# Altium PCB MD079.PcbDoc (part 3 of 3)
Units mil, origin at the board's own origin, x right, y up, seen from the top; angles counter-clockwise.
Board outline 4255 x 2850 mil, 4 copper layers (Top Layer, Ground, Power, Bottom Layer), stack 61.6 mil thick; 171 components, 88 nets, 422 pads, 405 vias.
Unrouted connection lines stored in the file: 3.
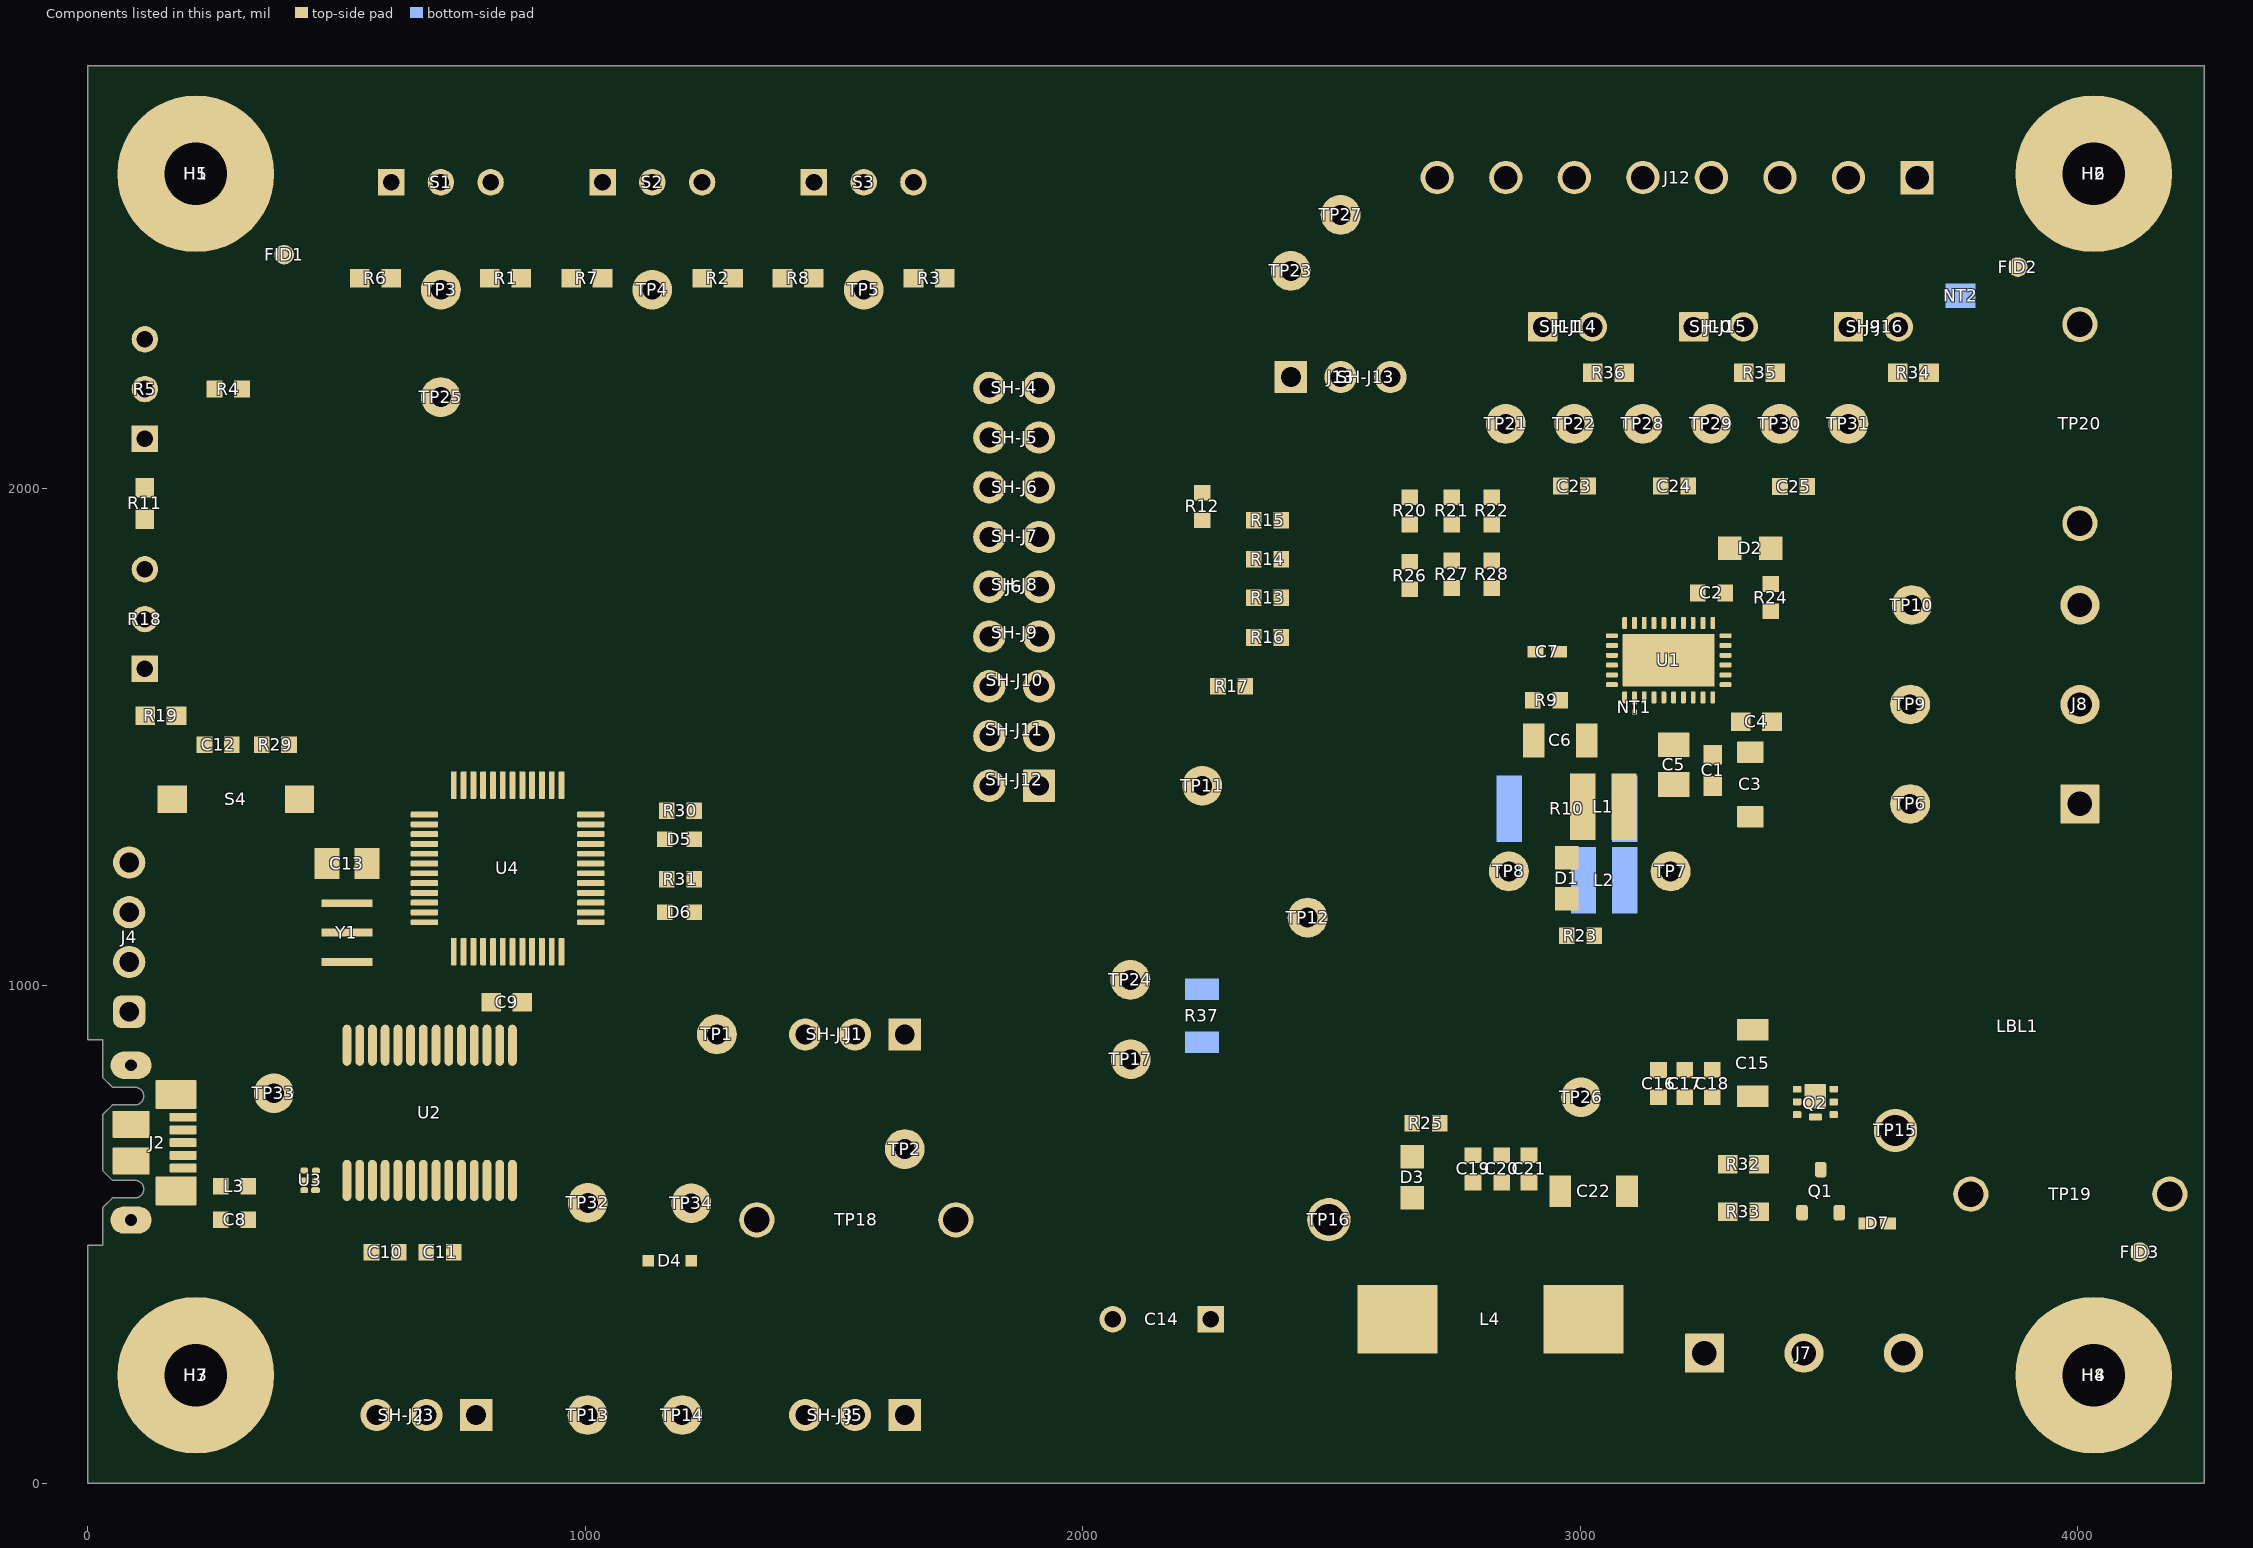
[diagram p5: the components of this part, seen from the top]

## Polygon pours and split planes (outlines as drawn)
VBK on Top Layer "TOP_LAYER_VBK_P051" (solid, remove dead copper, pour order 51): 2777.5,1175 3044.77,1175 3044.77,1452.44 3141.5,1560 3007.68,1560 2960.57,1512.89 2960.57,1435.66 2777.5,1275
NetD7_2 on Top Layer "TOP_LAYER_NETD7_2_P048" (solid, pour order 48): 3497.9,578.68 3497.9,500 3598.21,500 3598.21,578.68
NetQ1_1 on Top Layer "TOP_LAYER_NETQ1_1_P045" (solid, pour order 45): 3322.91,578.68 3322.91,500 3492.61,500 3492.61,578.68
5V_USB on Top Layer "TOP_LAYER_5V_USB_P043" (solid, pour order 43): 305,617.5 305,490 390,490 390,617.5
NetJ2_1 on Top Layer "TOP_LAYER_NETJ2_1_P044" (solid, remove dead copper, pour order 44): 170,650 340,650 340,565 170,565
NetC15_1 on Top Layer "TOP_LAYER_NETC15_1_P046" (solid, pour order 46): 3520,802.5 3130,802.5 3130,650 3422.5,650 3422.5,750 3520,750
NetQ1_3 on Top Layer "TOP_LAYER_NETQ1_3_P047" (solid, remove dead copper, pour order 47): 3322.91,685 3322.91,584.04 3517.5,584.04 3517.5,685 3450,685 3450,750 3422.5,750 3422.5,685
NetC15_1 on Top Layer "TOP_LAYER_NETC15_1_P049" (solid, pour order 49): 2830,490 3100,490 3100,232.5 2830,232.5
VM on Top Layer "TOP_LAYER_VM_P050" (solid, pour order 50): 2170,625 3000,625 3000,277.5 3187.5,277.5 3187.5,330 3317.5,330 3317.5,122.5 2170,122.5
PGND on Top Layer "TOP_LAYER_PGND_P070" (solid, remove dead copper, pour order 70): 4255,0 1865,0 1865,939.48 1864.48,940 3245.87,940 3245.87,1691.58 3767.5,2213.21 3767.5,2850 4255,2850
AGND on Top Layer "TOP_LAYER_AGND_P075" (solid, remove dead copper, pour order 75): 0,0 1865,0 1865,939.78 1865.22,940 3245.87,940 3245.87,1691.58 3767.5,2213.21 3767.5,2850 0,2850
AVDD on Top Layer "TOP_LAYER_AVDD_P066" (solid, pour order 66): 80,2132.5 150,2132.5 150,1965 80,1965
AVDD on Top Layer "TOP_LAYER_AVDD_P065" (solid, remove dead copper, pour order 65): 3217.71,1713.44 3239.75,1713.44 3239.75,1765.58 3240,1765.83 3269.86,1765.83 3269.86,1813.33 3327.5,1813.33 3327.5,1914.73 3217.71,1914.73
AVDD on Top Layer "TOP_LAYER_AVDD_P061" (solid, pour order 61): 2850.73,2030 2850.73,1965 2217.5,1965 2217.5,2030
OUTC on Top Layer "TOP_LAYER_OUTC_P057" (solid, pour order 57): 3275,1654.84 3401.91,1661.73 3600,1865 4120,1865 4120,1665 3600,1665 3420,1640 3275,1640
OUTA on Top Layer "TOP_LAYER_OUTA_P058" (solid, pour order 58): 3275,1612.5 3275,1595 3400,1585 3600,1265 4120,1265 4120,1465 3600,1465 3420,1612.5
OUTB on Top Layer "TOP_LAYER_OUTB_P056" (solid, pour order 56): 3275,1635 3420,1635 3600,1665 4120,1665 4120,1465 3600,1465 3420,1615 3275,1615
SW_BUCK on Top Layer "TOP_LAYER_SW_BUCK_P052" (solid, remove dead copper, pour order 52): 3050,1175 3240,1175 3240,1375 3150,1375 3150,1560 3050,1450
VM on Top Layer "TOP_LAYER_VM_P053" (solid, remove dead copper, pour order 53): 3220,1595 3220,1370 3400,1370 3400,1505 3351.12,1505 3351.12,1563.35 3260,1563.35 3260,1595
VBAT on Top Layer "TOP_LAYER_VBAT_P054" (solid, remove dead copper, pour order 54): 3605,580 3450,580 3450,802.5 3732.5,802.5 3732.5,172.5 3605,172.5
5VCC on Top Layer "TOP_LAYER_5VCC_P055" (solid, pour order 55): 605,490 705,490 705,442.5 605,442.5
AGND on Bottom Layer "BOTTOM_LAYER_AGND_P076" (solid, remove dead copper, pour order 76): 0,2850 3767.5,2850 3767.5,2203.16 3276.25,1711.91 3276.33,1047.64 3168.69,940 1865,940 1865,0 0,0
PGND on Bottom Layer "Bottom Layer-PGND" (solid, remove dead copper, pour order 74): 1865,940 1865,0 4255,0 4255,2850 3767.5,2850 3767.5,2203.16 3276.25,1711.91 3276.25,1049.4 3161.08,940
NetC15_1 on Bottom Layer "BOTTOM_LAYER_NETC15_1_P073" (solid, pour order 73): 2830,232.5 3155,232.5 3155,592.5 3422.5,592.5 3422.5,822.5 3130,822.5 3130,706.97 2830,706.97
5V_USB on Bottom Layer "BOTTOM_LAYER_5V_USB_P071" (solid, pour order 71): 440,495 315,495 315,840.51 440,840.51
VBK on Bottom Layer "BOTTOM_LAYER_VBK_P060" (solid, pour order 60): 3044.59,1450 2791.61,1450 2791.61,1137.5 3044.77,1137.5
SW_BUCK on Bottom Layer "BOTTOM_LAYER_SW_BUCK_P059" (solid, pour order 59): 3050,1450 3131.87,1450 3252.5,1330 3252.5,1137.5 3050,1137.5
AGND on Power "POWER_AGND_P069" (solid, remove dead copper, pour order 69): 0,2850 0,0 4255,0 4255,2850
VBK on Power "POWER_VBK_P068" (solid, remove dead copper, pour order 68): 2575,2297.5 2575,1540 2791.61,1275 2791.61,1152.5 2918.19,1152.5 2918.19,1275 2691.24,1540 2691.24,2297.5
AVDD on Power "POWER_AVDD_P067" (solid, pour order 67): 2837.5,1557.5 2876.25,1557.5 2876.25,1792.5 3292.5,1792.5 3292.5,2057.5 3757.5,2057.5 3757.5,2290.5 2864.88,2290.5 2739.8,2387.5 1879.47,2387.5 1783.18,2490 672.5,2490 320,2137.5 80,2137.5 80,2065 370.4,2065 612.34,2302.5 1835,2302.5 2252.5,2302.5 2252.5,1963.92 2307.5,1963.92 2307.5,2302.5 2700,2302.5 2785,2235 2785,2057.5 3207.85,2057.5 3207.85,1864.38 2837.5,1864.38
VM on Power "POWER_VM_P064" (solid, pour order 64): 2707.5,630 2170,630 2170,122.5 3387.5,122.5 3387.5,1477.5 3045,1477.5 3045,1015
5V_USB on Power "POWER_5V_USB_P063" (solid, pour order 63): 315,617.5 440,617.5 440,495 315,495
3V3_MCU on Power "POWER_3V3_MCU_P062" (solid, pour order 62): 1495,85 1595,85 1595,206.16 1272.5,526.21 1272.5,815 1150.3,937.2 1150.3,1395 1050,1395 1050,1277.5 512.5,1277.5 512.5,1470 415,1470 415,1100 46.93,1100 46.93,1000 512.5,1000 512.5,1180 1050,1180 1050,885 1157.5,777.5 1157.5,495 1495,157.5
AGND on Ground "GROUND_AGND_P072" (solid, remove dead copper, pour order 72): 0,2850 4255,2850 4255,0 0,0

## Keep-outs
Keep-Out Layer:
  text ".Layer_Name" at -201.73,-1117.79 h60

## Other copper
Top Layer:
  region net VBK: 3125,1560 3095,1560 3095,1545 3125,1545
  text ".Layer_Name" at -201.73,-1117.79 h60
Bottom Layer:
  text ".Layer_Name" at -201.73,-1117.79 h60

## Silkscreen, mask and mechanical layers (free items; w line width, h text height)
Top Overlay:
  lines w8: 505.04,61.69 846.71,61.38 846.96,406.6 505.28,406.91 505.04,63.84 ; 1367.28,62.4 1707.33,62.1 1707.57,412.11 1367.53,412.41 1367.28,64.56 ; 1862.5,2850 1865,7.5 ; 1907.28,2490.58 1908.82,2735.02 2194.64,2735.47 2193.1,2490.58 1909.15,2490.58 ; 1907.93,2607.88 2189.83,2607.77 ; 1909.15,2550.38 2193.48,2550.27 ; 1910.02,2672.75 2191.92,2672.64 ; 1967.06,2490.58 1969.83,2735.11 ; 1999.86,2703.14 2014.23,2715.19 ; 2000.27,2702.67 2013.22,2692.69 ; 2001.27,2703.14 2054.83,2702.69 ; 2077.09,2490.58 2077.33,2735.28 ; 2112.33,2705.52 2165.89,2705.08 ; 2152.93,2693.02 2167.3,2705.08 ; 2153.94,2715.52 2166.89,2705.55 ; 2238.36,1671.43 2238.36,1521.4 2565.58,1521.53 ; 2565.58,1671.75 2131.56,1671.33 2131.56,1821.4 2303.71,1821.4 2303.71,2017.8 2875,2017.8 2875.36,1445.36 ; 2565.58,2017.8 2565.58,1445.36 2777.5,1445.36 ; 2876.32,1925 3600,1925 3595,1301.26 3126.32,1301.26 3126.32,1445.36 2875.36,1445.36 ; 3542.81,1301.26 3542.81,1037.5 2777.5,1037.5 2777.5,1445.36 ; 2777.5,1445.36 2875.36,1445.36 ; 1366.05,761.65 1366.46,1214.26 1711.68,1214.02 1711.28,761.41 1366.05,761.65 ; 2345.82,2057.66 2346.03,2290.13 2691.25,2289.88 2691.05,2057.41 2345.82,2057.66
  text "HPWR" at 2646.14,2790 h30
  text "HNC" at 2811.14,2790 h30
  text "HPC" at 2951.14,2790 h30
  text "HNB" at 3091.14,2790 h30
  text "HPB" at 3223.64,2790 h30
  text "HNA" at 3366.14,2790 h30
  text "HPA" at 3501.14,2790 h30
  text "AGND" at 3636.14,2790 h30
  text "Switches" at 1937.33,2752.69 h30
  text "S" at 1929.83,2690.19 h30
  text "3" at 1927.45,2625.27 h30
  text "OFF" at 1982.33,2625.27 h30
  text "ON" at 2094.83,2625.27 h30
  text "2" at 1927.33,2562.77 h30
  text "ABC" at 1982.33,2562.77 h30
  text "ACB" at 2094.83,2562.77 h30
  text "1" at 1932.33,2502.69 h30
  text "BRK" at 1982.33,2502.69 h30
  text "RUN" at 2094.83,2502.69 h30
  text "Analog: connect to HPx and HNx, remove J9-J11" at 2512.44,2447.5 h30
  text "Digital: connect to HPx only, populate J9-J11" at 2512.44,2400 h30
  text "HALL_PWR_SEL" at 2298.77,2322.5 h40
  text "PWM" at 225.2,2255 h40
  text "AGND" at 1621.84,2184.91 h30
  text "AGND" at 2006.86,2184.91 h30
  text "HALL" at 2371.27,2129.13 h30
  text "VBK" at 2582.77,2112.68 h30
  text "MSP_nSLEEP" at 1442.5,2085.24 h30
  text "nSLEEP" at 2006.86,2085.24 h30
  text "EXT" at 2386.27,2080.24 h30
  text "MSP_nFAULT" at 1442.5,1985.56 h30
  text "nFAULT" at 2006.86,1985.56 h30
  text "SDO" at 2424.74,1923.54 h30
  text "MSP_SOMI" at 1510,1885.88 h30
  text "SOMI" at 2006.86,1885.88 h30
  text "nFAULT" at 3100.68,1864.3 h30
  text "SDI" at 2424.74,1845.35 h30
  text "ILIM" at 221.19,1805.4 h40
  text "MSP_SIMO" at 1510,1786.21 h30
  text "SIMO" at 2006.86,1786.21 h30
  text "SCLK" at 2424.74,1767.85 h30
  text "Pop." at 2189.83,1758.91 h30
  text "OUTC" at 4219.51,1707.59 h40 r90
  text "if SPI" at 2154.27,1700.64 h30
  text "nSCS" at 2424.74,1687.85 h30
  text "MSP_SCK" at 1532.5,1686.53 h30
  text "SCK" at 2006.86,1686.53 h30
  text "SLEW" at 2757.73,1660.26 h30 r90
  text "MODE" at 2835.3,1660.26 h30 r90
  text "DIR" at 2352.37,1590.01 h30
  text "MSP_STE" at 1532.5,1586.85 h30
  text "STE" at 2006.86,1586.85 h30
  text "ADVANCE" at 2671.63,1562.09 h30 r90
  text "Pop. if HW" at 2270,1544.35 h30
  text "HW Variant" at 2582.77,1504.25 h30
  text "OUTB" at 4219.51,1490.95 h40 r90
  text "MSP_PWM" at 1532.5,1487.18 h30
  text "PWM" at 2006.86,1487.18 h30
  text "Resistors" at 2597.5,1462.5 h30
  text "'.IC_Name'" at 3574.32,1403.23 h60 r90
  text "MSP_FGOUT" at 1472.5,1387.5 h30
  text "FGOUT" at 2006.86,1387.5 h30
  text "Depop. R13-R16" at 2353.96,1381.48 h30
  text "RST" at 469.95,1358.39 h30
  text "if HW variant" at 2370.28,1328.56 h30
  text "47uH" at 2857.43,1317.07 h30
  text "OUTA" at 4219.51,1275 h40 r90
  text "VBK" at 3021.76,1241.96 h30
  text "SBWTCK" at 170,1235 h30
  text "'.EVM_Orderable'" at 3589.75,1165.5 h50
  text "SBWTDIO" at 170,1135 h30
  text "Rev '.ROM_Rev'" at 3588.75,1101.78 h40
  text "Buck Reg." at 3183.85,1065.76 h40
  text "'.PRJ_Number'.PCB_Rev-'.Variant'" at 3587.75,1043.39 h30
  text "3.3V" at 170,1035 h30
  text "PWM_EXT" at 1652.7,991.2 h30 r90
  text "PWM_MSP" at 1456,982.5 h30 r90
  text "GND" at 170,935 h30
  text "PWM_SEL" at 1417.32,785 h40
  text "VM" at 2565,614.28 h30
  text "5V_USB" at 592.14,217.5 h30 r90
  text "5V_EXT" at 794.53,216.76 h30 r90
  text "3V3COM" at 1456,208.24 h30 r90
  text "3V3EXT" at 1657.5,207.5 h30 r90
  text "5V_SEL" at 475.89,125 h40 r90
  text "3V3_SEL" at 1770,112.5 h40 r90
  text "Connect to VM to bypass" at 2342.5,82.5 h35
  text "reverse polarity protection" at 2217.5,35 h35
  text "VM" at 3213.05,32.5 h40
  text "PGND" at 3375,32.5 h40
  text "VBAT" at 3575,32.5 h40
  text ".Layer_Name" at -201.73,-1117.79 h30
Bottom Overlay:
  lines w8: 2791.61,1082.01 3253.33,1082.01 3253.33,1504.25 2791.61,1504.25 2791.61,1082.01
  text "OUTC" at 3880,1752.5 h40
  text "OUTC" at 4207.5,1743.33 h40
  text "OUTB" at 3880,1545 h40
  text "OUTB" at 4207.5,1545 h40
  text "Buck Reg." at 3178.33,1531.45 h40
  text "22-ohm" at 3052.31,1445.36 h30
  text "OUTA" at 3880,1345 h40
  text "OUTA" at 4207.5,1345 h40
  text "22uH" at 3104.43,1100.05 h30
  text "Populate only L1 (top)," at 3331.85,1027.5 h30
  text "L2, or R10 for Buck Regulator." at 3457.6,972.76 h30
  text "VM" at 3282.5,150 h40
  text "PGND" at 3522.5,150 h40
  text "VBAT" at 3720.3,149.78 h40
  text ".Layer_Name" at -201.73,-1117.79 h60
Top Paste:
  text ".Layer_Name" at -201.73,-1117.79 h60
Bottom Paste:
  text ".Layer_Name" at -201.73,-1117.79 h60
Top Solder:
  text ".Layer_Name" at -201.73,-1117.79 h60
  text ".Layer_Name" at -201.73,-1117.79 h60
Bottom Solder:
  text ".Layer_Name" at -201.73,-1117.79 h60
Drill Guide:
  text ".Layer_Name" at -201.73,-1117.79 h60
M1 Board Outline:
  lines w4: 94.96,609.21 cw(c94.81,591.5) 94.96,573.78 49.68,573.78 30,554.09 30,478.31 0,478.31 0,0 4255,0 ; 94.96,609.21 94.96,609.21 ; 94.96,609.21 49.68,609.21 30,628.9 30,741.1 49.68,760.79 94.96,760.79 ccw(c94.85,778.5) 94.96,796.22 ; 94.96,796.22 94.96,796.22 ; 94.96,796.22 49.68,796.22 30,815.91 30,891.69 0,891.69 0,2850 4255,2850 4255,0 ; 4255,0 4255,0
  text ".Layer_Name" at -201.73,-1117.79 h60
M2 Board Dimensions:
  rectangle: -778.73,-534.3 -653.73,-409.3
  rectangle: -653.73,-659.3 -278.73,-534.3
  lines w7: -778.73,-534.3 221.27,-534.3 ; -653.73,-659.3 -653.73,-409.3 ; -528.73,-659.3 -528.73,-409.3 ; -278.73,-659.3 -278.73,-409.3 ; -28.73,-659.3 -28.73,-409.3 ; -778.73,-659.3 221.27,-659.3 221.27,-409.3 -778.73,-409.3 -778.73,-659.3
  text ".Layer_Name" at -201.73,-1117.79 h60
M3 3D STEP Top:
  text ".Layer_Name" at -201.73,-1117.79 h60
M4 3D STEP Bottom:
  text ".Layer_Name" at -201.73,-1117.79 h60
M5 Assembly Top:
  lines w10: -1070.73,-1189.46 5529.27,-1189.46 ; -1070.73,-986.13 5531.27,-986.13 ; -1070.73,-782.8 -1070.73,-1392.8 2934.27,-1392.8 5531.27,-1392.8 5531.27,-782.8 -1070.23,-782.8 -1070.23,-1392.8 505.27,-1392.8 ; 1394.27,-1392.8 1394.27,-782.8 ; 2661.27,-986.13 2661.27,-782.8 ; 3501.27,-986.13 3501.27,-782.8 ; 4123.27,-1399.3 4123.27,-1196.46
  text "COMPONENTS MARKED 'DNP' SHOULD NOT BE POPULATED." at 374.77,-577.8 h60
  text "ASSEMBLY VARIANT:" at 374.27,-693.3 h60
  text ".VariantName" at 1410.27,-693.3 h60
  text "PCB VIEWED FROM TOP SIDE" at -1007.23,-914.96 h60
  text "BOARD #:" at 1469.27,-914.96 h60
  text ".PRJ_Number" at 2014.77,-914.96 h60
  text "REV:" at 2859.27,-914.96 h60
  text ".PCB_Rev" at 3150.77,-914.96 h60
  text "SVN REV:" at 3697.27,-914.96 h60
  text ".VersionControl_RevNumber" at 4203.27,-914.96 h60
  text "TID #:" at 1469.27,-1118.3 h60
  text ".TID" at 2014.77,-1118.3 h60
  text "PLOT NAME =" at -1007.23,-1323.63 h60
  text ".plot_File_Name" at -201.73,-1323.63 h60
  text "GENERATED    :" at 1471.27,-1323.63 h60
  text ".Print_Date" at 2340.77,-1323.63 h60
  text ".Print_Time" at 3069.77,-1323.63 h60
  text "TEXAS INSTRUMENTS" at 4334.27,-1323.63 h60
M6 Assembly Bottom:
  lines w10: -1071.23,-986.63 5530.77,-986.63 ; -1069.23,-1189.96 5530.77,-1189.96 ; 336.77,-1399.8 336.77,-1196.96 ; 958.77,-986.63 958.77,-783.3 ; 1798.77,-986.63 1798.77,-783.3 ; 3065.77,-1393.3 3065.77,-783.3 ; 3954.77,-1393.3 5530.27,-1393.3 5530.27,-783.3 -1071.23,-783.3 -1071.23,-1393.3 1525.77,-1393.3 5530.77,-1393.3 5530.77,-783.3
  text "COMPONENTS MARKED 'DNP' SHOULD NOT BE POPULATED." at 5323.27,-577.3 h60
  text ".VariantName" at 4279.27,-693.3 h60
  text "ASSEMBLY VARIANT:" at 5318.27,-693.3 h60
  text ".VersionControl_RevNumber" at 256.77,-915.46 h60
  text "SVN REV:" at 762.77,-915.46 h60
  text ".PCB_Rev" at 1309.27,-915.46 h60
  text "REV:" at 1600.77,-915.46 h60
  text ".PRJ_Number" at 2445.27,-915.46 h60
  text "BOARD #:" at 2990.77,-915.46 h60
  text "PCB VIEWED FROM BOTTOM SIDE" at 5467.27,-915.46 h60
  text ".TID" at 2445.27,-1118.8 h60
  text "TID #:" at 2990.77,-1118.8 h60
  text "TEXAS INSTRUMENTS" at 125.77,-1324.13 h60
  text ".Print_Time" at 1390.27,-1324.13 h60
  text ".Print_Date" at 2119.27,-1324.13 h60
  text "GENERATED    :" at 2988.77,-1324.13 h60
  text ".plot_File_Name" at 4661.77,-1324.13 h60
  text "PLOT NAME =" at 5467.27,-1324.13 h60
M9 Title Sheet:
  drawing of 57 lines, arcs and shapes, not listed
  text "1" at -38.89,7777.2 h70
  text "2" at 2456.77,7777.2 h70
  text "3" at 4946.11,7777.2 h70
  text "4" at 7452.78,7777.2 h70
  text "5" at 9951.77,7777.2 h70
  text "6" at 12456.77,7777.2 h70
  text "A" at -1195.23,6634.2 h70
  text "A" at 13604.77,6634.2 h70
  text "B" at -1195.23,4254.2 h70
  text "B" at 13604.77,4254.2 h70
  text "C" at -1195.23,1879.2 h70
  text "C" at 13604.77,1879.2 h70
  text "PROJECT TITLE:" at 10564.77,18.2 h45
  text ".PRJ_Title" at 10614.77,-115.12 h70
  text "DESIGNED FOR:" at 10564.77,-282.8 h45
  text ".PRJ_Customer" at 10614.77,-422.8 h70
  text "D" at -1195.23,-490.8 h70
  text "D" at 13604.77,-490.8 h70
  text "FILE NAME:" at 10564.77,-582.8 h45
  text ".PCB_File_Name_No_Path" at 10614.77,-702.8 h70
  text "Texas Instruments (TI) and/or its licensors do not warrant the accuracy or completeness of this specification" at 5595.27,-864.63 h45
  text "ENGINEER:" at 10564.77,-872.8 h45
  text "LAYOUT BY:" at 12069.77,-872.8 h45
  text "or any information contained therein. TI and/or its licensors do not warrant that this design will meet" at 5550.28,-977.3 h45
  text ".PRJ_Engineer" at 10614.77,-1027.79 h70
  text ".PCB_Layout" at 12120.27,-1027.79 h70
  text "the specifications, will be suitable for your application or fit for any particular purpose, or will operate in" at 5550.28,-1089.97 h45
  text ".Layer_Name" at -201.73,-1117.79 h60
  text "ALTIUM DESIGNER VERSION:" at 12069.77,-1182.8 h45
  text "an implementation. TI and/or its licensors do not warrant that the design is production worthy. You should" at 5550.28,-1202.63 h45
  text "completely validate and test your design implementation to confirm the system functionality for your application." at 5595.27,-1315.3 h45
  text ".print_Scale" at 10614.77,-1316.12 h70
  text ".Application_BuildNumber" at 12120.27,-1316.12 h70
  text "1" at -38.89,-1522.8 h70
  text "2" at 2456.77,-1522.8 h70
  text "3" at 4946.11,-1522.8 h70
  text "4" at 7452.78,-1522.8 h70
  text "5" at 9951.77,-1522.8 h70
  text "6" at 12456.77,-1522.8 h70
M10 Fab Notes:
  drawing of 189 lines, arcs and shapes, not listed
  text "DESIGN INFORMATION" at 11603.29,6096.88 h60
  text "MIN. TRACK WIDTH:" at 10958.73,5964.75 h60
  text "8" at 12054.97,5964.75 h60
  text "MIL" at 12209.73,5964.75 h60
  text "MIN. CLEARANCE:" at 10958.73,5840.63 h60
  text "0.2" at 11994.97,5840.63 h60
  text "mm" at 12209.73,5840.63 h60
  text "MIN. VIA PAD SIZE:" at 10958.73,5716.5 h60
  text "20" at 12024.98,5716.5 h60
  text "MIL" at 12209.73,5716.5 h60
  text "0.05mm (2MIL)" at 11653.73,5586.6 h60
  text "MINIMUM ANNULAR RING" at 10629.5,5578.38 h60
  text "EXTERNAL" at 12361.73,5578.38 h60
  text "PER" at 10829.5,5468.25 h60
  text "IPC-D-275 CLASS 2 LEVEL C" at 11049.5,5468.25 h60
  text "MIL, HOLES" at 12537.73,5367.77 h60
  text "+/-" at 12145.27,5359.19 h60
  text "+/-" at 12999.27,5359.19 h60
  text "REGISTRATION TOLERANCES:" at 10629.5,5358.12 h60
  text "METAL" at 11829.27,5358.12 h60
  text "5" at 12405.47,5358.12 h60
  text "3" at 13238.47,5358.12 h60
  text "MIL" at 13354.73,5358.12 h60
  text "HOLE SIZE TOLERANCE (UNLESS OTHERWISE SPECIFIED):" at 10629.5,5259.81 h60
  text "+/-" at 12999.27,5256.93 h60
  text "3" at 13238.47,5255.87 h60
  text "MIL" at 13354.73,5255.87 h60
  text "MATERIAL:" at 10554.73,5118.22 h60
  text "FR-4 High Tg" at 11541.17,4989.7 h60
  text "X" at 11396.73,4981.71 h60
  text "FR-408" at 10975.73,4977.19 h60
  text "OTHER" at 12463.73,4977.19 h60
  text "62 MIL (1.6mm) +/-10%" at 11295.83,4834.16 h60
  text "X" at 11175.73,4831.71 h60
  text "THICKNESS:" at 10629.5,4825.94 h60
  text "OTHER" at 12580.73,4825.94 h60
  text "TOLERANCE:" at 10629.5,4687.63 h60
  text "X" at 11477.73,4687.63 h60
  text "ANSI IPC-6012 TYPE 3 CLASS 2" at 11655.75,4687.63 h60
  text "OTHER +/-" at 11655.73,4543.44 h60
  text "BOW & TWIST:" at 10629.5,4398.25 h60
  text "X" at 11477.73,4398.25 h60
  text "ANSI IPC-6012 TYPE 3 CLASS 2" at 11655.75,4398.25 h60
  text "OTHER +/-" at 11655.73,4251.55 h60
  text "DRILLING:" at 10554.73,4120.93 h60
  text "NC_DRILL FILES" at 12315.73,4015.74 h60
  text "REFERENCE:" at 10629.5,4011.81 h60
  text "X" at 11286.73,4011.71 h60
  text "AS SHOWN" at 11464.73,4011.81 h60
  text "X" at 12187.73,4011.81 h60
  text "OTHER" at 12613.73,3869.55 h60
  text "PTH COPPER THICKNESS:" at 10629.18,3866.03 h60
  text "X" at 11768.41,3866.03 h60
  text "20-30 um" at 11896.41,3866.03 h60
  text "BOARD FINISH:" at 10554.73,3718.43 h60
  text "SILKSCREEN:" at 10709.95,3608.3 h60
  text "X" at 11667.73,3608.3 h60
  text "TOP" at 11784.73,3608.3 h60
  text "X" at 12177.73,3608.3 h60
  text "BOTTOM" at 12295.73,3608.3 h60
  text "SILKSCREEN COLOR:" at 10709.95,3453.11 h60
  text "X" at 11666.73,3453.11 h60
  text "WHITE" at 11784.73,3453.11 h60
  text "OTHER" at 12295.73,3453.11 h60
  text "X" at 11797.73,3309.67 h60
  text "GREEN" at 11915.73,3309.67 h60
  text "OTHER" at 12533.73,3309.67 h60
  text "SOLDER RESIST COLOR:" at 10709.95,3302.8 h60
  text "X" at 11797.73,3155.41 h60
  text "MATTE" at 11915.73,3155.41 h60
  text "SEMI-GLOSS" at 12533.27,3154.78 h60
  text "IMMERSION GOLD (ENIG)" at 11615.73,2982.64 h60
  text "ENEPIG" at 12953.27,2975.42 h60
  text "SURFACE FINISH:" at 10554.73,2974.42 h60
  text "X" at 11437.73,2974.42 h60
  text "IMM. TIN/SILVER OR EQUIV" at 10884.27,2837.11 h60
  text "OTHER" at 12315.73,2833.17 h60
  text "ARRAY/PANEL:" at 10554.73,2677.79 h60
  text "CUT AND TRIM PER M1 BOARD OUTLINE" at 11615.73,2669.57 h60
  text "N.C. ROUTE" at 11615.73,2533.6 h60
  text "X" at 12303.73,2533.6 h60
  text "V. SCORE" at 12481.73,2533.6 h60
  text "CERTIFICATION:" at 10554.73,2404.48 h60
  text "MATERIALS AND WORKMANSHIP FOR ALL PCBS" at 11279.73,2404.48 h60
  text "TO MEET OR EXCEED THE REQUIREMENTS OF:" at 11279.73,2310.41 h60
  text "X" at 10917.24,2181.78 h60
  text "ANSI IPC-A-600F CLASS ->" at 11045.23,2181.78 h60
  text "X" at 12693.24,2181.78 h60
  text "2" at 12803.23,2181.78 h60
  text "1" at 12488.23,2180.29 h60
  text "3" at 13157.23,2180.29 h60
  text "X" at 11729.24,2034.1 h60
  text "RoHS" at 11857.23,2034.1 h60
  text "OTHER" at 12501.63,2034.1 h60
  text "PER ORDER" at 12898.69,2034.1 h60
  text "ALL BOARDS MUST MEET OR EXCEED UL94-V0 REQUIREMENTS." at 10582.27,1880.27 h60
  text "PCB MUST BEAR THE UL94V-0 UL REGISTERED MATERIAL ID NUMBER" at 10582.27,1764.21 h60
  text "ADDITIONAL REQUIREMENTS:" at 10554.73,1594.78 h60
  text "MICROSECTION:" at 10629.5,1487.66 h60
  text "YES" at 11535.23,1487.66 h60
  text "REQUIRED" at 12396.73,1343.32 h60
  text "BARE BOARD ELEC. TEST:" at 10629.5,1340.47 h60
  text "NONE" at 11935.23,1340.47 h60
  text "X" at 12278.73,1340.47 h60
  text "PER ORDER" at 12988.73,1340.47 h60
  text "XX MIL VIAS REQUIRE NON-CONDUCTIVE FILL AND PLANARIZE" at 10797.65,1135.52 h59
  text "XX MIL VIAS REQUIRE CONDUCTIVE FILL AND PLANARIZE" at 10805.65,1031.55 h60
  text "OUTER XX MIL TRACES REQUIRE 50 OHM SINGLE-ENDED IMPEDANCE" at 10804.66,868.16 h58
  text "LAYER 2 & 3 (INNER LAYERS) XX MIL WIDE, XX MIL SPACE / TRACES REQUIRE 100 OHM DIFFERENTIAL IMPEDANCE" at 10796.66,632.45 h60
  text ".Layer_Name" at -201.73,-1117.79 h60
M11 Gerber Information:
  lines w10: -1070.73,-1189.46 5529.27,-1189.46 ; -1070.73,-986.13 5531.27,-986.13 ; -1070.73,-782.8 -1070.73,-1392.8 2934.27,-1392.8 5531.27,-1392.8 5531.27,-782.8 -1070.23,-782.8 -1070.23,-1392.8 505.27,-1392.8 ; 1394.27,-1392.8 1394.27,-782.8 ; 2661.27,-986.13 2661.27,-782.8 ; 3501.27,-986.13 3501.27,-782.8 ; 4123.27,-1399.3 4123.27,-1196.46
  text "ALL ARTWORK VIEWED FROM TOP SIDE" at -1007.23,-914.96 h60
  text "BOARD #:" at 1469.27,-914.96 h60
  text ".PRJ_Number" at 2014.77,-914.96 h60
  text "REV:" at 2859.27,-914.96 h60
  text ".PCB_Rev" at 3150.77,-914.96 h60
  text "SVN REV:" at 3697.27,-914.96 h60
  text ".VersionControl_RevNumber" at 4203.27,-914.96 h60
  text "LAYER NAME =" at -1007.23,-1117.79 h60
  text "TID #:" at 1469.27,-1118.3 h60
  text ".TID" at 2014.77,-1118.3 h60
  text "PLOT NAME =" at -1007.23,-1323.63 h60
  text ".plot_File_Name" at -201.73,-1323.63 h60
  text "GENERATED    :" at 1471.27,-1323.63 h60
  text ".Print_Date" at 2340.77,-1323.63 h60
  text ".Print_Time" at 3069.77,-1323.63 h60
  text "TEXAS INSTRUMENTS" at 4334.27,-1323.63 h60
M12 Stackup:
  drawing of 295 lines, arcs and shapes, not listed
  text "Layer" at 5343.26,5772.51 h60
  text "Name" at 5753.18,5772.51 h60
  text "Material" at 6682.92,5772.51 h60
  text "Thickness" at 7542.69,5772.51 h60
  text "Constant" at 8192.52,5772.51 h60
  text "Board Layer Stack" at 8762.39,5772.51 h60
  text "Top Overlay" at 5753.18,5652.51 h60
  text "Top Solder" at 5753.18,5532.51 h60
  text "Solder Resist" at 6682.92,5532.51 h60
  text "0.40mil" at 7542.69,5532.51 h60
  text "3.5" at 8192.52,5532.51 h60
  text "1" at 5343.26,5412.51 h60
  text "Top Layer" at 5753.18,5412.51 h60
  text "1.40mil" at 7542.69,5412.51 h60
  text "Dielectric 1" at 5753.18,5292.51 h60
  text "FR-4" at 6682.92,5292.51 h60
  text "8.00mil" at 7542.69,5292.51 h60
  text "4.2" at 8192.52,5292.51 h60
  text "2" at 5343.26,5172.51 h60
  text "Ground" at 5753.18,5172.51 h60
  text "1.40mil" at 7542.69,5172.51 h60
  text "Dielectric 2" at 5753.18,5052.51 h60
  text "FR-4" at 6682.92,5052.51 h60
  text "40.00mil" at 7542.69,5052.51 h60
  text "4.2" at 8192.52,5052.51 h60
  text "3" at 5343.26,4932.51 h60
  text "Power" at 5753.18,4932.51 h60
  text "1.40mil" at 7542.69,4932.51 h60
  text "Dielectric 3" at 5753.18,4812.51 h60
  text "FR-4" at 6682.92,4812.51 h60
  text "8.00mil" at 7542.69,4812.51 h60
  text "4.2" at 8192.52,4812.51 h60
  text "4" at 5343.26,4692.51 h60
  text "Bottom Layer" at 5753.18,4692.51 h60
  text "1.40mil" at 7542.69,4692.51 h60
  text "Bottom Solder" at 5753.18,4572.51 h60
  text "Solder Resist" at 6682.92,4572.51 h60
  text "0.40mil" at 7542.69,4572.51 h60
  text "3.5" at 8192.52,4572.51 h60
  text "Bottom Overlay" at 5753.18,4452.51 h60
  text ".Layer_Name" at -201.73,-1117.79 h60
M13 Component Bodies Top:
  text ".Layer_Name" at -201.73,-1117.79 h60
M14 Component Bodies Bottom:
  text ".Layer_Name" at -201.73,-1117.79 h60
M15 Courtyards Top:
  text ".Layer_Name" at -201.73,-1117.79 h60
M16 Courtyards Bottom:
  text ".Layer_Name" at -201.73,-1117.79 h60
Drill Drawing:
  circle w10: c5363.72,3403.68 r16.58
  circle w10: c5363.72,3403.68 r27.63
  circle w10: c5363.72,3279.36 r27.63
  lines w10: 5336.09,2906.4 5363.72,2878.78 5391.34,2906.4 5363.72,2934.03 5336.09,2906.4 ; 5336.09,3016.91 5349.9,3016.91 5349.9,3003.1 5377.53,3003.1 5377.53,3016.91 5391.34,3016.91 5391.34,3044.54 5377.53,3044.54 5377.53,3058.35 5349.9,3058.35 5349.9,3044.54 5336.09,3044.54 5336.09,3016.91 ; 5336.09,3127.42 5391.34,3127.42 5391.34,3182.67 5336.09,3182.67 5336.09,3127.42 ; 5336.09,3500.38 5363.72,3514.19 5391.34,3500.38 5377.53,3528 5391.34,3555.63 5363.72,3541.82 5336.09,3555.63 5349.9,3528 5336.09,3500.38 ; 5336.09,3638.51 5349.9,3638.51 5363.72,3624.7 5377.53,3638.51 5391.34,3638.51 5377.53,3652.32 5391.34,3666.14 5377.53,3666.14 5363.72,3679.95 5349.9,3666.14 5336.09,3666.14 5349.9,3652.32 5336.09,3638.51 ; 5336.09,3804.27 5391.34,3804.27 5363.72,3749.02 5336.09,3804.27 ; 5336.09,3873.34 5336.09,3887.15 5349.9,3900.96 5336.09,3914.78 5336.09,3928.59 5349.9,3928.59 5363.72,3914.78 5377.53,3928.59 5391.34,3928.59 5391.34,3914.78 5377.53,3900.96 5391.34,3887.15 5391.34,3873.34 5377.53,3873.34 5363.72,3887.15 5349.9,3873.34 5336.09,3873.34 ; 5336.09,3997.66 5391.34,3997.66 5391.34,4052.91 5336.09,4052.91 5336.09,3997.66 ; 5347.14,4008.71 5380.29,4008.71 5380.29,4041.86 5347.14,4041.86 5347.14,4008.71
  lines w12: 5286,2841.48 8517.49,2841.48 ; 5286,4084.68 8517.49,4084.68 ; 5623.86,2717.16 5623.86,4209 ; 5955.86,2717.16 5955.86,4209 ; 6592.43,2717.16 6592.43,4209 ; 6851.57,2717.16 6851.57,4209 ; 7226.72,2717.16 7226.72,4209 ; 7951.05,2717.16 7951.05,4209 ; 5286,2717.16 8517.49,2717.16 8517.49,4209 5286,4209 5286,2717.16
  text "Symbol" at 5360.59,4121.98 h72
  text "Quantity" at 5661.16,4121.98 h72
  text "Finished Hole Size" at 5993.16,4121.98 h72
  text "Plated" at 6629.72,4121.98 h72
  text "Hole Type" at 6888.86,4121.98 h72
  text "Drill Layer Pair" at 7264.02,4121.98 h72
  text "Hole Tolerance" at 7988.35,4121.98 h72
  text "11" at 5661.16,3997.66 h60
  text "7.87mil (0.200mm)" at 5993.16,3997.66 h60
  text "PTH" at 6629.72,3997.66 h60
  text "Round" at 6888.86,3997.66 h60
  text "Top Layer - Bottom Layer" at 7264.02,3997.66 h60
  text "394" at 5661.16,3873.34 h60
  text "10.00mil (0.254mm)" at 5993.16,3873.34 h60
  text "PTH" at 6629.72,3873.34 h60
  text "Round" at 6888.86,3873.34 h60
  text "Top Layer - Bottom Layer" at 7264.02,3873.34 h60
  text "17" at 5661.16,3749.02 h60
  text "33.47mil (0.850mm)" at 5993.16,3749.02 h60
  text "PTH" at 6629.72,3749.02 h60
  text "Round" at 6888.86,3749.02 h60
  text "Top Layer - Bottom Layer" at 7264.02,3749.02 h60
  text "69" at 5661.16,3624.7 h60
  text "40.00mil (1.016mm)" at 5993.16,3624.7 h60
  text "PTH" at 6629.72,3624.7 h60
  text "Round" at 6888.86,3624.7 h60
  text "Top Layer - Bottom Layer" at 7264.02,3624.7 h60
  text "8" at 5661.16,3500.38 h60
  text "47.24mil (1.200mm)" at 5993.16,3500.38 h60
  text "PTH" at 6629.72,3500.38 h60
  text "Round" at 6888.86,3500.38 h60
  text "Top Layer - Bottom Layer" at 7264.02,3500.38 h60
  text "6" at 5661.16,3376.06 h60
  text "49.21mil (1.250mm)" at 5993.16,3376.06 h60
  text "PTH" at 6629.72,3376.06 h60
  text "Round" at 6888.86,3376.06 h60
  text "Top Layer - Bottom Layer" at 7264.02,3376.06 h60
  text "6" at 5661.16,3251.74 h60
  text "51.18mil (1.300mm)" at 5993.16,3251.74 h60
  text "PTH" at 6629.72,3251.74 h60
  text "Round" at 6888.86,3251.74 h60
  text "Top Layer - Bottom Layer" at 7264.02,3251.74 h60
  text "2" at 5661.16,3127.42 h60
  text "63.00mil (1.600mm)" at 5993.16,3127.42 h60
  text "PTH" at 6629.72,3127.42 h60
  text "Round" at 6888.86,3127.42 h60
  text "Top Layer - Bottom Layer" at 7264.02,3127.42 h60
  text "4" at 5661.16,3003.1 h60
  text "125.98mil (3.200mm)" at 5993.16,3003.1 h60
  text "PTH" at 6629.72,3003.1 h60
  text "Round" at 6888.86,3003.1 h60
  text "Top Layer - Bottom Layer" at 7264.02,3003.1 h60
  text "2" at 5661.16,2878.78 h60
  text "23.62mil (0.600mm)" at 5993.16,2878.78 h60
  text "PTH" at 6629.72,2878.78 h60
  text "Slot" at 6888.86,2878.78 h60
  text "Top Layer - Bottom Layer" at 7264.02,2878.78 h60
  text "519 Total" at 5661.16,2754.46 h60
  text "Slot definitions :" at 5360.59,2667.43 h60
  text "Routed Path Length" at 5811.31,2667.43 h60
  text "= Calculated from tool start centre position to tool end centre position." at 6351.05,2667.43 h60
  text "Hole Length" at 5811.31,2617.7 h60
  text "= Routed Path Length + Tool Size = Slot length as defined in the PCB layout" at 6151.25,2617.7 h60
  text ".Layer_Name" at -201.73,-1117.79 h60
Mechanical 17:
  text ".Layer_Name" at -201.73,-1117.79 h60
Mechanical 18:
  text ".Layer_Name" at -201.73,-1117.79 h60
Mechanical 19:
  text ".Layer_Name" at -201.73,-1117.79 h60

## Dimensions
-778.73,-659.3 to 221.27,-659.3 on M2 Board Dimensions
-14.92,2850 to 30,554.09 on M2 Board Dimensions
30,554.09 to 0,478.31 on M2 Board Dimensions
